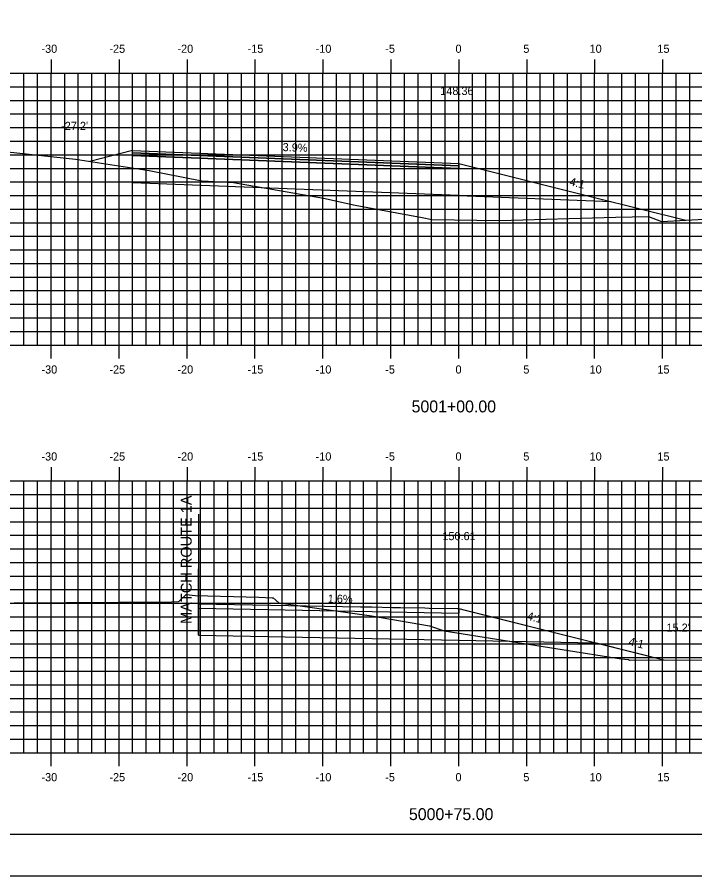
# Model space of a CAD drawing. Extents: x 850973 to 851145, y 365876 to 365986.
# Drawn here: x 851023.9 to 851073.8, y 365875.8 to 365939 of the extents above; entities that cross this region are included whole.
import ezdxf

# ---------------------------------------------------------------- set-up
doc = ezdxf.new("R2010")
doc.units = 0
for name, color, linetype in [('ANNOTATION', 7, 'Continuous'), ('BORDER', 7, 'Continuous'), ('D_Roadway_Centerline', 7, 'Continuous'), ('D_Roadway_Centerline_Text', 7, 'Continuous'), ('D_Roadway_Edge_TW', 7, 'Continuous'), ('D_Roadway_FinishedGrade', 7, 'Continuous'), ('D_Roadway_Pavement', 7, 'Continuous'), ('D_Roadway_SlopeLines', 7, 'Continuous'), ('D_Roadway_SubGrade', 7, 'Continuous'), ('D_Text_Standard', 7, 'Continuous'), ('H_V ANNOTATION', 7, 'Continuous'), ('MAJOR', 7, 'Continuous'), ('MINOR', 7, 'Continuous'), ('PLOT BOUNDARY', 7, 'Continuous'), ('S_Roadway_Centerline', 7, 'Continuous')]:
    doc.layers.add(name, color=color, linetype=linetype)

msp = doc.modelspace()

# ---------------------------------------------------------------- linework, layer by layer
at = {"layer": 'ANNOTATION'}
msp.add_line((851037.235, 365895.794), (851037.235, 365898.375), dxfattribs=at)
at = {"layer": 'BORDER'}
msp.add_lwpolyline([(850981.386, 365878.833), (851141.386, 365878.833), (851141.386, 365983.833), (850981.386, 365983.833)], close=True, dxfattribs=at)
at = {"layer": 'D_Roadway_Centerline'}
for points in [[(851032.385, 365929.134), (851056.385, 365928.196), (851066.385, 365925.696), (851073.107, 365924.016)], [(851037.235, 365895.794), (851049.162, 365895.579), (851050.01, 365895.556), (851051.519, 365895.53), (851052.105, 365895.515), (851053.891, 365895.484), (851054.2, 365895.477), (851056.282, 365895.444), (851056.295, 365895.443), (851056.385, 365895.442), (851056.845, 365895.327), (851066.385, 365892.942), (851066.615, 365892.885), (851071.564, 365891.647)]]:
    msp.add_lwpolyline(points, dxfattribs=at)
at = {"layer": 'D_Roadway_Edge_TW'}
msp.add_lwpolyline([(851032.385, 365929.134), (851056.385, 365928.196), (851056.385, 365928.029), (851032.385, 365928.967)], close=True, dxfattribs=at)
at = {"layer": 'D_Roadway_FinishedGrade'}
for p, q in [((851032.385, 365929.134), (851029.226, 365928.344)), ((851056.385, 365925.829), (851067.606, 365925.391)), ((851056.385, 365895.442), (851056.385, 365895.108)), ((851056.385, 365893.108), (851066.406, 365892.916))]:
    msp.add_line(p, q, dxfattribs=at)
for points in [[(851037.235, 365893.476), (851037.235, 365895.794)], [(851037.235, 365895.476), (851056.385, 365895.108)], [(851037.235, 365893.476), (851056.385, 365893.108)]]:
    msp.add_lwpolyline(points, dxfattribs=at)
at = {"layer": 'D_Roadway_Pavement'}
msp.add_lwpolyline([(851032.385, 365928.967), (851056.385, 365928.029), (851056.385, 365927.829), (851032.385, 365928.767)], close=True, dxfattribs=at)
for points in [[(851056.385, 365928.029), (851056.385, 365927.829)], [(851056.385, 365928.029), (851056.385, 365927.829)], [(851056.385, 365895.275), (851056.385, 365895.109)], [(851056.385, 365895.275), (851056.385, 365895.109)]]:
    msp.add_lwpolyline(points, dxfattribs=at)
at = {"layer": 'D_Roadway_SlopeLines'}
for points in [[(851056.385, 365928.196), (851066.385, 365925.696), (851073.107, 365924.016)], [(851056.385, 365895.442), (851066.385, 365892.942), (851071.564, 365891.647)], [(851056.385, 365895.442), (851066.385, 365892.942)], [(851056.385, 365895.442), (851066.385, 365892.942)]]:
    msp.add_lwpolyline(points, dxfattribs=at)
at = {"layer": 'D_Roadway_SubGrade'}
msp.add_line((851037.235, 365902.393), (851037.235, 365893.476), dxfattribs=at)
msp.add_lwpolyline([(851056.385, 365925.829), (851032.385, 365926.767), (851032.385, 365928.767), (851056.385, 365927.829)], dxfattribs=at)
at = {"layer": 'MAJOR'}
for p, q in [((851026.385, 365935.835), (851026.385, 365934.833)), ((851031.385, 365935.835), (851031.385, 365934.833)), ((851036.385, 365935.835), (851036.385, 365934.833)), ((851041.385, 365935.835), (851041.385, 365934.833)), ((851046.385, 365935.835), (851046.385, 365934.833)), ((851051.385, 365935.835), (851051.385, 365934.833)), ((851056.385, 365935.835), (851056.385, 365934.833)), ((851061.385, 365935.835), (851061.385, 365934.833)), ((851066.385, 365935.835), (851066.385, 365934.833)), ((851071.385, 365935.835), (851071.385, 365934.833)), ((850986.385, 365934.833), (851126.385, 365934.833)), ((850986.385, 365934.833), (851126.385, 365934.833)), ((851026.385, 365914.833), (851026.385, 365934.833)), ((851031.385, 365914.833), (851031.385, 365934.833)), ((851036.385, 365914.833), (851036.385, 365934.833)), ((851041.385, 365914.833), (851041.385, 365934.833)), ((851046.385, 365914.833), (851046.385, 365934.833)), ((851051.385, 365914.833), (851051.385, 365934.833)), ((851056.385, 365914.833), (851056.385, 365934.833)), ((851061.385, 365914.833), (851061.385, 365934.833)), ((851066.385, 365914.833), (851066.385, 365934.833)), ((851071.385, 365914.833), (851071.385, 365934.833)), ((850986.385, 365929.833), (851126.385, 365929.833)), ((850986.385, 365924.833), (851126.385, 365924.833)), ((850986.385, 365919.833), (851126.385, 365919.833)), ((850986.385, 365914.833), (851126.385, 365914.833)), ((850986.385, 365914.833), (851126.385, 365914.833)), ((851026.385, 365913.831), (851026.385, 365914.833)), ((851031.385, 365913.831), (851031.385, 365914.833)), ((851036.385, 365913.831), (851036.385, 365914.833)), ((851041.385, 365913.831), (851041.385, 365914.833)), ((851046.385, 365913.831), (851046.385, 365914.833)), ((851051.385, 365913.831), (851051.385, 365914.833)), ((851056.385, 365913.831), (851056.385, 365914.833)), ((851061.385, 365913.831), (851061.385, 365914.833)), ((851066.385, 365913.831), (851066.385, 365914.833)), ((851071.385, 365913.831), (851071.385, 365914.833)), ((851026.385, 365905.835), (851026.385, 365904.833)), ((851031.385, 365905.835), (851031.385, 365904.833)), ((851036.385, 365905.835), (851036.385, 365904.833)), ((851041.385, 365905.835), (851041.385, 365904.833)), ((851046.385, 365905.835), (851046.385, 365904.833)), ((851051.385, 365905.835), (851051.385, 365904.833)), ((851056.385, 365905.835), (851056.385, 365904.833)), ((851061.385, 365905.835), (851061.385, 365904.833)), ((851066.385, 365905.835), (851066.385, 365904.833)), ((851071.385, 365905.835), (851071.385, 365904.833)), ((850986.385, 365904.833), (851126.385, 365904.833)), ((850986.385, 365904.833), (851126.385, 365904.833)), ((851026.385, 365884.833), (851026.385, 365904.833)), ((851031.385, 365884.833), (851031.385, 365904.833)), ((851036.385, 365884.833), (851036.385, 365904.833)), ((851041.385, 365884.833), (851041.385, 365904.833)), ((851046.385, 365884.833), (851046.385, 365904.833)), ((851051.385, 365884.833), (851051.385, 365904.833)), ((851056.385, 365884.833), (851056.385, 365904.833)), ((851061.385, 365884.833), (851061.385, 365904.833)), ((851066.385, 365884.833), (851066.385, 365904.833)), ((851071.385, 365884.833), (851071.385, 365904.833)), ((850986.385, 365899.833), (851126.385, 365899.833)), ((850986.385, 365894.833), (851126.385, 365894.833)), ((850986.385, 365889.833), (851126.385, 365889.833)), ((850986.385, 365884.833), (851126.385, 365884.833)), ((850986.385, 365884.833), (851126.385, 365884.833)), ((851026.385, 365883.831), (851026.385, 365884.833)), ((851031.385, 365883.831), (851031.385, 365884.833)), ((851036.385, 365883.831), (851036.385, 365884.833)), ((851041.385, 365883.831), (851041.385, 365884.833)), ((851046.385, 365883.831), (851046.385, 365884.833)), ((851051.385, 365883.831), (851051.385, 365884.833)), ((851056.385, 365883.831), (851056.385, 365884.833)), ((851061.385, 365883.831), (851061.385, 365884.833)), ((851066.385, 365883.831), (851066.385, 365884.833)), ((851071.385, 365883.831), (851071.385, 365884.833))]:
    msp.add_line(p, q, dxfattribs=at)
at = {"layer": 'MINOR'}
for p, q in [((851024.385, 365914.833), (851024.385, 365934.833)), ((851025.385, 365914.833), (851025.385, 365934.833)), ((851027.385, 365914.833), (851027.385, 365934.833)), ((851028.385, 365914.833), (851028.385, 365934.833)), ((851029.385, 365914.833), (851029.385, 365934.833)), ((851030.385, 365914.833), (851030.385, 365934.833)), ((851032.385, 365914.833), (851032.385, 365934.833)), ((851033.385, 365914.833), (851033.385, 365934.833)), ((851034.385, 365914.833), (851034.385, 365934.833)), ((851035.385, 365914.833), (851035.385, 365934.833)), ((851037.385, 365914.833), (851037.385, 365934.833)), ((851038.385, 365914.833), (851038.385, 365934.833)), ((851039.385, 365914.833), (851039.385, 365934.833)), ((851040.385, 365914.833), (851040.385, 365934.833)), ((851042.385, 365914.833), (851042.385, 365934.833)), ((851043.385, 365914.833), (851043.385, 365934.833)), ((851044.385, 365914.833), (851044.385, 365934.833)), ((851045.385, 365914.833), (851045.385, 365934.833)), ((851047.385, 365914.833), (851047.385, 365934.833)), ((851048.385, 365914.833), (851048.385, 365934.833)), ((851049.385, 365914.833), (851049.385, 365934.833)), ((851050.385, 365914.833), (851050.385, 365934.833)), ((851052.385, 365914.833), (851052.385, 365934.833)), ((851053.385, 365914.833), (851053.385, 365934.833)), ((851054.385, 365914.833), (851054.385, 365934.833)), ((851055.385, 365914.833), (851055.385, 365934.833)), ((851057.385, 365914.833), (851057.385, 365934.833)), ((851058.385, 365914.833), (851058.385, 365934.833)), ((851059.385, 365914.833), (851059.385, 365934.833)), ((851060.385, 365914.833), (851060.385, 365934.833)), ((851062.385, 365914.833), (851062.385, 365934.833)), ((851063.385, 365914.833), (851063.385, 365934.833)), ((851064.385, 365914.833), (851064.385, 365934.833)), ((851065.385, 365914.833), (851065.385, 365934.833)), ((851067.385, 365914.833), (851067.385, 365934.833)), ((851068.385, 365914.833), (851068.385, 365934.833)), ((851069.385, 365914.833), (851069.385, 365934.833)), ((851070.385, 365914.833), (851070.385, 365934.833)), ((851072.385, 365914.833), (851072.385, 365934.833)), ((851073.385, 365914.833), (851073.385, 365934.833)), ((850986.385, 365933.833), (851126.385, 365933.833)), ((850986.385, 365932.833), (851126.385, 365932.833)), ((850986.385, 365931.833), (851126.385, 365931.833)), ((850986.385, 365930.833), (851126.385, 365930.833)), ((850986.385, 365928.833), (851126.385, 365928.833)), ((850986.385, 365927.833), (851126.385, 365927.833)), ((850986.385, 365926.833), (851126.385, 365926.833)), ((850986.385, 365925.833), (851126.385, 365925.833)), ((850986.385, 365923.833), (851126.385, 365923.833)), ((850986.385, 365922.833), (851126.385, 365922.833)), ((850986.385, 365921.833), (851126.385, 365921.833)), ((850986.385, 365920.833), (851126.385, 365920.833)), ((850986.385, 365918.833), (851126.385, 365918.833)), ((850986.385, 365917.833), (851126.385, 365917.833)), ((850986.385, 365916.833), (851126.385, 365916.833)), ((850986.385, 365915.833), (851126.385, 365915.833)), ((851024.385, 365884.833), (851024.385, 365904.833)), ((851025.385, 365884.833), (851025.385, 365904.833)), ((851027.385, 365884.833), (851027.385, 365904.833)), ((851028.385, 365884.833), (851028.385, 365904.833)), ((851029.385, 365884.833), (851029.385, 365904.833)), ((851030.385, 365884.833), (851030.385, 365904.833)), ((851032.385, 365884.833), (851032.385, 365904.833)), ((851033.385, 365884.833), (851033.385, 365904.833)), ((851034.385, 365884.833), (851034.385, 365904.833)), ((851035.385, 365884.833), (851035.385, 365904.833)), ((851037.385, 365884.833), (851037.385, 365904.833)), ((851038.385, 365884.833), (851038.385, 365904.833)), ((851039.385, 365884.833), (851039.385, 365904.833)), ((851040.385, 365884.833), (851040.385, 365904.833)), ((851042.385, 365884.833), (851042.385, 365904.833)), ((851043.385, 365884.833), (851043.385, 365904.833)), ((851044.385, 365884.833), (851044.385, 365904.833)), ((851045.385, 365884.833), (851045.385, 365904.833)), ((851047.385, 365884.833), (851047.385, 365904.833)), ((851048.385, 365884.833), (851048.385, 365904.833)), ((851049.385, 365884.833), (851049.385, 365904.833)), ((851050.385, 365884.833), (851050.385, 365904.833)), ((851052.385, 365884.833), (851052.385, 365904.833)), ((851053.385, 365884.833), (851053.385, 365904.833)), ((851054.385, 365884.833), (851054.385, 365904.833)), ((851055.385, 365884.833), (851055.385, 365904.833)), ((851057.385, 365884.833), (851057.385, 365904.833)), ((851058.385, 365884.833), (851058.385, 365904.833)), ((851059.385, 365884.833), (851059.385, 365904.833)), ((851060.385, 365884.833), (851060.385, 365904.833)), ((851062.385, 365884.833), (851062.385, 365904.833)), ((851063.385, 365884.833), (851063.385, 365904.833)), ((851064.385, 365884.833), (851064.385, 365904.833)), ((851065.385, 365884.833), (851065.385, 365904.833)), ((851067.385, 365884.833), (851067.385, 365904.833)), ((851068.385, 365884.833), (851068.385, 365904.833)), ((851069.385, 365884.833), (851069.385, 365904.833)), ((851070.385, 365884.833), (851070.385, 365904.833)), ((851072.385, 365884.833), (851072.385, 365904.833)), ((851073.385, 365884.833), (851073.385, 365904.833)), ((850986.385, 365903.833), (851126.385, 365903.833)), ((850986.385, 365902.833), (851126.385, 365902.833)), ((850986.385, 365901.833), (851126.385, 365901.833)), ((850986.385, 365900.833), (851126.385, 365900.833)), ((850986.385, 365898.833), (851126.385, 365898.833)), ((850986.385, 365897.833), (851126.385, 365897.833)), ((850986.385, 365896.833), (851126.385, 365896.833)), ((850986.385, 365895.833), (851126.385, 365895.833)), ((850986.385, 365893.833), (851126.385, 365893.833)), ((850986.385, 365892.833), (851126.385, 365892.833)), ((850986.385, 365891.833), (851126.385, 365891.833)), ((850986.385, 365890.833), (851126.385, 365890.833)), ((850986.385, 365888.833), (851126.385, 365888.833)), ((850986.385, 365887.833), (851126.385, 365887.833)), ((850986.385, 365886.833), (851126.385, 365886.833)), ((850986.385, 365885.833), (851126.385, 365885.833))]:
    msp.add_line(p, q, dxfattribs=at)
at = {"layer": 'PLOT BOUNDARY'}
msp.add_lwpolyline([(850973.292, 365875.774), (851143.292, 365875.774), (851143.292, 365985.774), (850973.292, 365985.774)], close=True, dxfattribs=at)
at = {"layer": 'S_Roadway_Centerline'}
for points in [[(850986.385, 365928.832), (850997.86, 365928.864), (851000.484, 365928.869), (851001.333, 365928.852), (851014.684, 365928.898), (851015.507, 365928.967), (851015.893, 365929.281), (851016.145, 365929.486), (851019.302, 365929.578), (851019.379, 365929.574), (851023.183, 365929.056), (851028.186, 365928.504), (851033.588, 365927.674), (851037.474, 365926.925), (851039.808, 365926.786), (851046.433, 365925.629), (851048.76, 365925.118), (851053.69, 365924.218), (851054.402, 365924.069), (851059.389, 365923.99), (851067.935, 365924.248), (851070.348, 365924.286), (851071.299, 365923.923), (851074.89, 365924.107)], [(851023.657, 365895.853), (851035.244, 365895.939), (851035.761, 365895.951), (851035.797, 365895.984), (851036.333, 365896.467), (851036.975, 365896.411), (851041.671, 365896.273), (851042.652, 365896.236), (851042.714, 365896.229), (851043.139, 365895.852), (851049.971, 365894.9), (851054.229, 365894.178), (851055.306, 365893.802), (851068.349, 365891.738), (851068.879, 365891.694), (851068.958, 365891.637), (851076.022, 365891.665)]]:
    msp.add_lwpolyline(points, dxfattribs=at)

# ---------------------------------------------------------------- texts
at = {"layer": 'ANNOTATION'}
for s, height, rotation, p in [('3.9%', 0.6, 357.76222, (851043.414, 365929.104)), ('4:1', 0.6, 345.96376, (851064.499, 365926.598)), ('MATCH ROUTE 1A', 0.8, 90, (851036.728, 365894.311)), ('1.6%', 0.6, 359.0908, (851046.74, 365895.873)), ('4:1', 0.6, 345.96216, (851061.368, 365894.627)), ('4:1', 0.6, 345.9581, (851068.843, 365892.758))]:
    msp.add_text(s, height=height, rotation=rotation, dxfattribs=at).set_placement(p)
at = {"layer": 'D_Roadway_Centerline_Text'}
for s, p in [('148.36', (851055.021, 365933.228)), ('150.61', (851055.176, 365900.474))]:
    msp.add_text(s, height=0.6, dxfattribs=at).set_placement(p)
at = {"layer": 'D_Text_Standard'}
for s, p in [("-27.2'", (851027.121, 365930.655)), ("15.2'", (851071.67, 365893.735))]:
    msp.add_text(s, height=0.6, dxfattribs=at).set_placement(p)
at = {"layer": 'H_V ANNOTATION'}
for s, height, p in [('-30', 0.6, (851025.673, 365936.333)), ('-25', 0.6, (851030.671, 365936.333)), ('-20', 0.6, (851035.679, 365936.333)), ('-15', 0.6, (851040.842, 365936.333)), ('-10', 0.6, (851045.85, 365936.333)), ('-5', 0.6, (851050.976, 365936.333)), ('0', 0.6, (851056.144, 365936.333)), ('5', 0.6, (851061.136, 365936.333)), ('10', 0.6, (851066.011, 365936.333)), ('15', 0.6, (851071.003, 365936.333)), ('-30', 0.6, (851025.673, 365912.733)), ('-25', 0.6, (851030.671, 365912.733)), ('-20', 0.6, (851035.679, 365912.733)), ('-15', 0.6, (851040.842, 365912.733)), ('-10', 0.6, (851045.85, 365912.733)), ('-5', 0.6, (851050.976, 365912.733)), ('0', 0.6, (851056.144, 365912.733)), ('5', 0.6, (851061.136, 365912.733)), ('10', 0.6, (851066.011, 365912.733)), ('15', 0.6, (851071.003, 365912.733)), ('5001+00.00', 0.875, (851052.913, 365909.876)), ('-30', 0.6, (851025.673, 365906.333)), ('-25', 0.6, (851030.671, 365906.333)), ('-20', 0.6, (851035.679, 365906.333)), ('-15', 0.6, (851040.842, 365906.333)), ('-10', 0.6, (851045.85, 365906.333)), ('-5', 0.6, (851050.976, 365906.333)), ('0', 0.6, (851056.144, 365906.333)), ('5', 0.6, (851061.136, 365906.333)), ('10', 0.6, (851066.011, 365906.333)), ('15', 0.6, (851071.003, 365906.333)), ('-30', 0.6, (851025.673, 365882.733)), ('-25', 0.6, (851030.671, 365882.733)), ('-20', 0.6, (851035.679, 365882.733)), ('-15', 0.6, (851040.842, 365882.733)), ('-10', 0.6, (851045.85, 365882.733)), ('-5', 0.6, (851050.976, 365882.733)), ('0', 0.6, (851056.144, 365882.733)), ('5', 0.6, (851061.136, 365882.733)), ('10', 0.6, (851066.011, 365882.733)), ('15', 0.6, (851071.003, 365882.733)), ('5000+75.00', 0.875, (851052.717, 365879.876))]:
    msp.add_text(s, height=height, dxfattribs=at).set_placement(p)

doc.saveas('drawing.dxf')
